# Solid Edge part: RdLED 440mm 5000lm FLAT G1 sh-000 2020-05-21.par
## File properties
Author: sylwester.cabaj
Template: iso metric part.par
Last saved by: sylwester.cabaj
Revision: 2
Application: Solid Edge
Gęstość: 0,000 kg/m^3
Dokładność: 0,990
Username: sylwester.cabaj
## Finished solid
Body 1: solid body, 5801 faces, 15187 edges, 10053 vertices.
  Faces by surface: plane 5541, cylinder 126, spline 80, cone 26, torus 11, sphere 10, spun 7
  Edges by curve: line 14624, curve on surface 282, circle 171, ellipse 66, spline 38, intersection 6
Bounding box of the edges (mm; curved faces can reach further): 428.000 x 428.000 x 4.450, from (-214, -214, -1) to (214, 214, 3.45).
Cylindrical faces by radius (mm): R0.2 x39, R0.2002 x2, R0.2169 x3, R0.25 x12, R0.3 x2, R0.3373 x3, R0.4 x8, R0.4006 x2, R0.4008 x2, R0.525 x2, R0.6 x12, R1 x7, R1.0894 x2, R1.1 x14, R2.15 x12, R220 x4
Conical faces (half-angle, radius in mm at the cone's reference point): 0.5 deg R0.5056 x4, 0.5 deg R1.0082 x4, 1 deg R0.5511 x2, 10 deg R0.2132 x2, 10 deg R0.4132 x2, 18.4844 deg R1.0657 x4, 27.363 deg R0.6214 x2, 45 deg R0.575 x2, 45 deg R0.625 x4
Toroidal faces (ring radius, tube radius in mm): R0.1 r0.2 x1, R0.8 r0.2 x4, R0.8522 r0.3 x2, R0.9002 r0.2 x1, R0.9018 r0.2 x1, R1.3 r0.2 x2
Spherical faces by radius (mm): R0.2 x8, R0.6 x2
Planar faces by outward normal: +x 47, +y 42, +z 1028, -x 38, -y 42, -z 8, oblique 4336
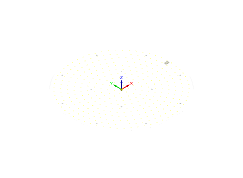
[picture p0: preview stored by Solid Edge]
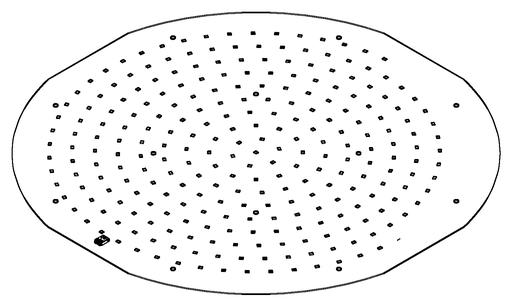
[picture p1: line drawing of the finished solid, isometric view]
